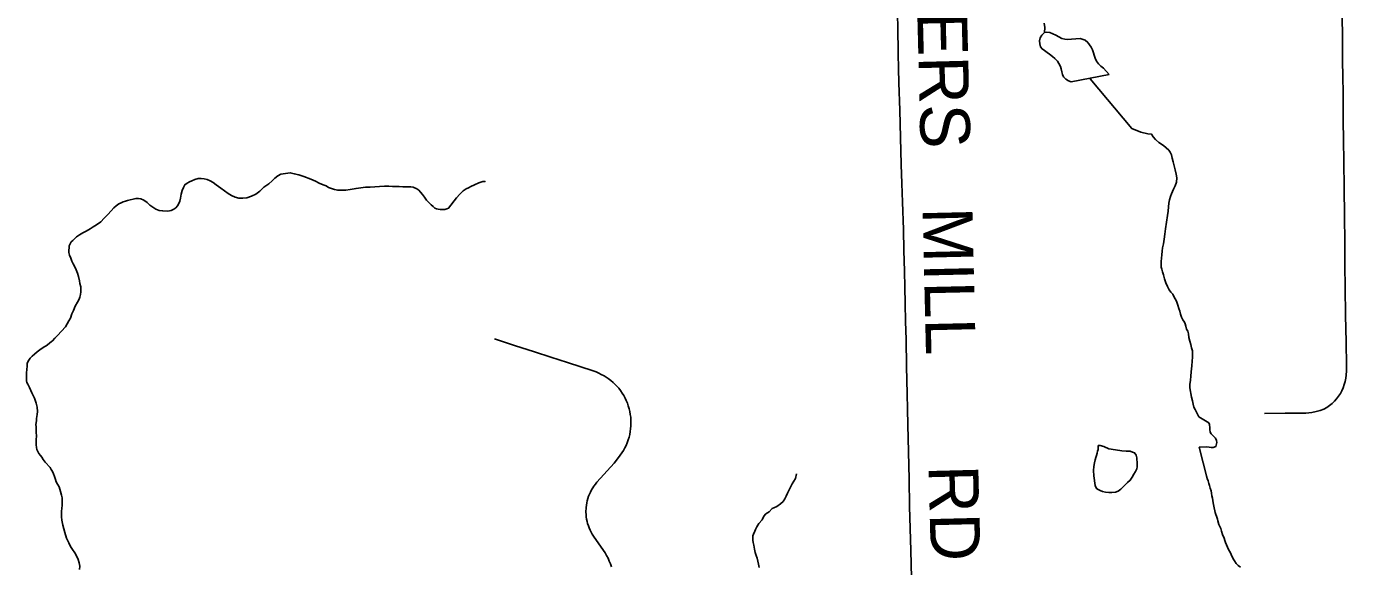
# Model space of a CAD drawing. Extents: x 103424 to 286016, y 38711 to 110967.
# Drawn here: x 125365 to 133370, y 84863 to 88138 of the extents above; entities that cross this region are included whole.
import ezdxf

# ---------------------------------------------------------------- set-up
doc = ezdxf.new("R2010")
doc.units = 0
for name, color, linetype in [('GM_X_Minor_Lake', 7, 'Continuous'), ('GM_X_Minor_River', 7, 'Continuous'), ('GM_X_Township_Road', 7, 'Continuous'), ('GM_X_Township_Road_Text', 7, 'Continuous')]:
    doc.layers.add(name, color=color, linetype=linetype)

msp = doc.modelspace()

# ---------------------------------------------------------------- linework, layer by layer
at = {"layer": 'GM_X_Minor_Lake'}
msp.add_line((131700.9, 87802.5), (131930.2, 87846.7), dxfattribs=at)
for points in [[(131753.7, 88065), (131675.8, 88058.2), (131661.7, 88060.1), (131643.5, 88064), (131607.2, 88083.9), (131570.8, 88099.8), (131552.7, 88101.7), (131538.6, 88099.6), (131522.6, 88085.4), (131512.7, 88069.2), (131508.8, 88051), (131510.9, 88032.9), (131515, 88014.7), (131523.2, 88000.7), (131537.3, 87990.7), (131553.5, 87978.7), (131567.7, 87968.7), (131585.9, 87954.7), (131600.1, 87942.7), (131616.3, 87926.7), (131624.4, 87912.7), (131634.6, 87894.6), (131638.7, 87880.5), (131642.9, 87862.4), (131647, 87846.3), (131653.2, 87832.2), (131667.4, 87818.2), (131683.5, 87808.2), (131700.9, 87802.5)], [(131930.2, 87846.7), (131896.4, 87884.3), (131880.2, 87896.3), (131866, 87910.3), (131853.8, 87926.3), (131845.6, 87944.4), (131839.5, 87962.5), (131835.4, 87976.6), (131829.2, 87994.7), (131821, 88010.8), (131810.9, 88026.8), (131800.7, 88040.9), (131784.5, 88054.9), (131753.7, 88065)], [(131863.7, 85596.2), (131864, 85571.9), (131860, 85561.8), (131858.2, 85549.7), (131854.3, 85535.5), (131850.4, 85523.3), (131844.5, 85509.1), (131840.7, 85490.9), (131836.9, 85468.7), (131835.2, 85444.4), (131837.5, 85412.1), (131846.3, 85353.6), (131852.6, 85335.5), (131862.7, 85329.5), (131874.9, 85323.6), (131889.1, 85317.7), (131907.4, 85313.8), (131927.6, 85312), (131945.7, 85312.2), (131967.9, 85314.4), (131984, 85320.6), (132002.1, 85332.9), (132014.1, 85343.2), (132028, 85357.4), (132042, 85371.7), (132058, 85386), (132069.9, 85404.3), (132079.8, 85422.6), (132089.7, 85438.9), (132097.6, 85455.1), (132099.5, 85467.2), (132099.3, 85481.4), (132099.2, 85495.5), (132099, 85511.7), (132098.8, 85521.8), (132094.6, 85537.9), (132084.4, 85551.9), (132072.2, 85555.8), (132058, 85561.8), (132047.9, 85561.7), (132033.8, 85561.5), (132007.5, 85565.3), (131969.4, 85569.6)], [(131969.4, 85569.6), (131928.5, 85576.6), (131898.1, 85590.5), (131875.8, 85596.3), (131863.7, 85596.2)]]:
    msp.add_lwpolyline(points, dxfattribs=at)
at = {"layer": 'GM_X_Minor_River'}
for points in [[(131537.1, 88156.4), (131539.4, 88130.2), (131538.6, 88099.6)], [(131814.2, 87820.5), (132067.6, 87519.3), (132122.4, 87495.6), (132164.9, 87485.9), (132187.2, 87484.1), (132197.5, 87468.1), (132211.8, 87452.1), (132232.2, 87434.1), (132260.7, 87416.2), (132277, 87402.2), (132291.3, 87388.2), (132299.5, 87374.2), (132307.8, 87358.1), (132312.1, 87337.9), (132318.4, 87315.8), (132324.7, 87291.6), (132331.1, 87267.4), (132337.4, 87241.2), (132339.7, 87219), (132338, 87192.7), (132330.2, 87170.4), (132320.3, 87150.1), (132314.4, 87135.9), (132308.5, 87121.7), (132302.7, 87105.5), (132296.8, 87085.3), (132293, 87065), (132289.2, 87042.8), (132287.5, 87016.5), (132283.8, 86990.2), (132272.6, 86909.3), (132268.9, 86878.9), (132263.2, 86848.6), (132259.5, 86820.2), (132253.7, 86795.9), (132251.9, 86775.7), (132250.2, 86753.5), (132248.4, 86733.3), (132246.6, 86713.1), (132244.8, 86694.9), (132245, 86678.7), (132249.2, 86666.6), (132253.4, 86650.5), (132259.7, 86630.4), (132266, 86606.2), (132274.4, 86582), (132284.7, 86559.9), (132295.1, 86539.8), (132305.3, 86525.8), (132315.6, 86513.7), (132321.8, 86499.7), (132330.1, 86485.6), (132338.3, 86471.6), (132342.5, 86459.5), (132346.6, 86447.4), (132352.9, 86427.3), (132359.2, 86411.2), (132363.4, 86393), (132369.7, 86374.9), (132378, 86358.8), (132386.2, 86344.8), (132390.4, 86334.7), (132394.6, 86320.6), (132398.8, 86302.5), (132407, 86290.4), (132411.3, 86274.3), (132413.6, 86252.1), (132419.9, 86230), (132426.1, 86209.8), (132430.4, 86189.7), (132434.7, 86171.5), (132434.9, 86153.3), (132435.1, 86133.1), (132433.4, 86108.9), (132431.7, 86080.6), (132428.1, 86044.2), (132426.4, 86017.9), (132422.6, 85993.6), (132418.9, 85967.3), (132419.1, 85947.1), (132429.9, 85890.7), (132436.2, 85866.5), (132440.5, 85846.4), (132444.7, 85828.2), (132450.9, 85814.1), (132473.2, 85770.8)], [(125400.3, 86137.9), (125414.3, 86150.2), (125430.2, 86164.5), (125446.3, 86176.7), (125466.3, 86191.1), (125490.4, 86205.5), (125506.4, 86219.8), (125522.4, 86232.1), (125538.3, 86248.4), (125554.3, 86262.7), (125602.2, 86315.7), (125612.1, 86333.9), (125622, 86352.2), (125631.9, 86368.5), (125639.6, 86394.8), (125651.5, 86415.1), (125661.3, 86441.5), (125675.2, 86465.9), (125685.1, 86484.2), (125689, 86496.3), (125692.8, 86512.5), (125694.7, 86528.7), (125694.5, 86542.8), (125694.3, 86559), (125690, 86579.2), (125687.8, 86595.3), (125681.5, 86621.5), (125675.2, 86641.6), (125666.9, 86661.7), (125658.6, 86679.8), (125648.3, 86697.9), (125640, 86714), (125633.7, 86732.1), (125627.4, 86750.2), (125623.2, 86766.4), (125623.1, 86780.5), (125624.9, 86794.7), (125624.8, 86806.8), (125630.7, 86819), (125636.6, 86831.1), (125646.6, 86839.3), (125656.6, 86849.5), (125668.6, 86861.8), (125686.6, 86874.1), (125706.7, 86886.4), (125726.7, 86896.7), (125750.8, 86911.1), (125770.9, 86921.4), (125790.9, 86933.7), (125817, 86952.1), (125836.9, 86974.5), (125858.9, 86997), (125878.8, 87019.4), (125894.8, 87037.7), (125908.8, 87050), (125924.8, 87062.3), (125938.8, 87068.5), (125950.9, 87074.7), (125965, 87078.8), (125977.1, 87083), (126029.4, 87093.6), (126045.6, 87093.8), (126059.8, 87091.9), (126078, 87084), (126096.4, 87070), (126112.7, 87054), (126131, 87042.1), (126149.3, 87030.2), (126169.6, 87022.3), (126191.9, 87018.5), (126222.2, 87016.8), (126242.3, 87021), (126258.4, 87029.2), (126270.4, 87037.4), (126280.4, 87049.7), (126290.3, 87063.9), (126296.2, 87078.1), (126300.1, 87096.3), (126303.8, 87120.6), (126309.6, 87142.9), (126317.5, 87161.1), (126325.4, 87177.4), (126339.4, 87187.6), (126353.4, 87195.8), (126367.5, 87202), (126385.6, 87210.3), (126405.7, 87214.5), (126423.9, 87214.7), (126442.1, 87212.9), (126460.3, 87209), (126478.6, 87201.1), (126496.9, 87191.2), (126515.2, 87177.2), (126543.7, 87157.3), (126566.1, 87141.4), (126588.5, 87125.4), (126608.9, 87111.5), (126631.2, 87101.6), (126653.5, 87095.8), (126677.7, 87096), (126702, 87098.3)], [(126702, 87098.3), (126730.1, 87108.7), (126756.2, 87121.1), (126780.3, 87139.5), (126804.2, 87163.9), (126834.3, 87182.4), (126854.3, 87200.8), (126872.3, 87217.1), (126890.3, 87231.5), (126908.3, 87241.7), (126964.8, 87250.4), (126989.1, 87244.6), (127017.5, 87236.8), (127047.9, 87227), (127090.5, 87211.2), (127118.9, 87199.4), (127141.2, 87187.5), (127163.6, 87177.6), (127181.8, 87171.7), (127196.1, 87161.8), (127214.3, 87153.9), (127232.6, 87148), (127252.8, 87144.2), (127277.1, 87144.4), (127301.3, 87144.6), (127327.5, 87148.9), (127363.8, 87155.4), (127392, 87159.7), (127420.3, 87162), (127448.5, 87162.3), (127476.8, 87164.6), (127507, 87166.9), (127537.3, 87169.2), (127563.6, 87169.5), (127585.8, 87167.7), (127606, 87167.9), (127626.2, 87166.1), (127648.5, 87164.3), (127664.6, 87164.4), (127682.8, 87164.6), (127696.9, 87164.7), (127711.1, 87162.9), (127733.4, 87153), (127743.6, 87145), (127753.8, 87133), (127766.1, 87119), (127778.4, 87102.9), (127790.8, 87084.9), (127807.1, 87068.9), (127819.4, 87054.9), (127831.6, 87044.9), (127841.8, 87034.9), (127852, 87030.9), (127862.1, 87029), (127874.2, 87027.1), (127888.4, 87027.3), (127902.5, 87027.4), (127914.6, 87031.6), (127924.6, 87035.7), (127972.4, 87098.8), (127992.3, 87121.2), (128014.3, 87141.6), (128032.4, 87151.9), (128046.4, 87158.1), (128060.5, 87166.3), (128082.6, 87176.7), (128108.7, 87189), (128132.8, 87197.4), (128146.9, 87197.5), (128146.9, 87197.5)], [(125687.9, 84843.9), (125689.7, 84866.1), (125685.4, 84886.3), (125679.1, 84906.4), (125668.8, 84928.5), (125658.5, 84946.6), (125644.1, 84966.7), (125631.8, 84984.7), (125621.4, 85006.8), (125609, 85035), (125598.5, 85069.2), (125585.8, 85113.6), (125579.4, 85143.8), (125577.2, 85164), (125577, 85182.2), (125578.8, 85198.3), (125580.6, 85214.5), (125582.4, 85234.7), (125582.1, 85259), (125581.9, 85279.2), (125577.7, 85295.3), (125571.3, 85317.4), (125562.9, 85345.6), (125552.7, 85361.7), (125546.4, 85375.8), (125542.2, 85389.9), (125536, 85408), (125529.7, 85424.1), (125523.5, 85438.2), (125515.3, 85450.2), (125509.1, 85462.3), (125478.4, 85496.3), (125466.1, 85512.3), (125457.8, 85526.4), (125449.6, 85536.4), (125441.4, 85548.5), (125435.2, 85560.5), (125429, 85572.6), (125426.9, 85584.7), (125424.7, 85600.8), (125424.3, 85631.1), (125426.1, 85655.4), (125423.8, 85675.5), (125423.6, 85693.7), (125423.4, 85709.9), (125423.2, 85724), (125425.1, 85734.1), (125427, 85748.3), (125426.9, 85760.4), (125428.7, 85772.6), (125430.6, 85784.7), (125432.4, 85802.9), (125430.1, 85829.1), (125423.8, 85853.3), (125413.3, 85883.5), (125398.8, 85915.7), (125384.3, 85947.9), (125374, 85968), (125367.8, 85978), (125365.6, 85988.1), (125365.4, 86008.3), (125365.1, 86036.6), (125366.9, 86056.8), (125368.7, 86077), (125370.5, 86093.2), (125374.4, 86103.3), (125380.3, 86113.5), (125388.3, 86125.7), (125400.3, 86137.9)], [(132473.2, 85770.8), (132534.4, 85734.1), (132538.6, 85724.1), (132541, 85703.9), (132541.2, 85693.8), (132543.5, 85677.7), (132549.7, 85667.7), (132562.1, 85653.8), (132574.4, 85641.9), (132580.7, 85627.9), (132583, 85615.8), (132577.3, 85591.4), (132561.3, 85585.1), (132549.2, 85584.9), (132537.1, 85586.7), (132522.9, 85588.5), (132477.1, 85586.3)], [(132477.1, 85586.3), (132524.3, 85396.6), (132520, 85414.7), (132524.3, 85396.6), (132530.7, 85382.5), (132535, 85366.5), (132539.2, 85354.4), (132543.5, 85338.3), (132547.9, 85322.2), (132550.1, 85308.1), (132552.5, 85292), (132556.7, 85278), (132559, 85263.8), (132561.3, 85249.8), (132563.5, 85239.7), (132565.7, 85229.6), (132572.4, 85191.4), (132576.7, 85179.3), (132580.9, 85167.3), (132587.3, 85149.2), (132589.5, 85139.1), (132596, 85117), (132602.2, 85105), (132606.5, 85093), (132610.8, 85076.9), (132617.2, 85056.8), (132627.7, 85034.8), (132632, 85020.7), (132636.2, 85008.7), (132642.5, 84994.6), (132648.8, 84980.6), (132653.1, 84966.6), (132659.4, 84956.6), (132667.7, 84942.6), (132671.9, 84930.5), (132678.2, 84920.5), (132682.4, 84910.5), (132690.7, 84896.5), (132701.1, 84880.6), (132713.4, 84868.7), (132727.7, 84858.8)], [(130033.8, 85424.5), (130028, 85396.1), (130018.1, 85379.9), (130008.2, 85363.6), (129980.6, 85306.8), (129972.7, 85288.5), (129964.8, 85274.3), (129952.9, 85258), (129936.9, 85243.7), (129914.9, 85227.3), (129896.8, 85219.1), (129886.7, 85214.9), (129868.8, 85194.5), (129848.7, 85182.2), (129836.8, 85168), (129826.9, 85145.7), (129807, 85123.2), (129793.1, 85102.9), (129785.2, 85086.7), (129781.3, 85076.5), (129773.4, 85058.3), (129769.5, 85048.1), (129769.7, 85034), (129769.8, 85021.9), (129772, 85007.7), (129776.2, 84991.6), (129780.5, 84967.4), (129784.8, 84947.3), (129789, 84929.1), (129795.3, 84913), (129799.5, 84894.9), (129803.8, 84876.7), (129808.1, 84856.6)]]:
    msp.add_lwpolyline(points, dxfattribs=at)
at = {"layer": 'GM_X_Township_Road'}
for points in [[(130732.3, 84795.1), (130727.7, 84960.1), (130723.9, 85093.9), (130720.2, 85227.7), (130716.8, 85392.8), (130713.3, 85557.8), (130709.9, 85722.8), (130707.9, 85816.2), (130706, 85909.7), (130702.3, 86074.7), (130698.6, 86239.8), (130696.1, 86349), (130693.6, 86458.3), (130691.1, 86555.7), (130688.6, 86653.2), (130685.7, 86779.8), (130682.8, 86906.5), (130677, 87071.5), (130673.1, 87185.5), (130669.1, 87299.6), (130664.6, 87464.6), (130660.1, 87629.6), (130655.6, 87794.6), (130653.2, 87882.7), (130650.8, 87970.9), (130648, 88135.9), (130645.8, 88271.4)], [(132871.4, 85790.5), (132997.5, 85791.8), (133123.6, 85793), (133158.4, 85796.8), (133185, 85802.5), (133209.7, 85809), (133231.4, 85817.6), (133249.8, 85827.4), (133266.2, 85838.6), (133281.6, 85851), (133295.9, 85864.6), (133309, 85879.3), (133321.1, 85895), (133332.5, 85912.4), (133341.3, 85929), (133349.3, 85947), (133355.9, 85965.6), (133360.9, 85984.7), (133364.7, 86004.2), (133366.7, 86023.8), (133369.2, 86049.2), (133370, 86082.2), (133366.7, 86222.4), (133364.4, 86387.5), (133362.2, 86552.5), (133360.3, 86689), (133358.5, 86825.6), (133356.6, 86990.7), (133354.8, 87155.7), (133352.9, 87320.8), (133351.5, 87444.9), (133350.1, 87569), (133348.3, 87734.1), (133347.2, 87832.8), (133346.1, 87931.4), (133344.6, 88067.4), (133343, 88203.5)], [(128912.1, 84861.8), (128906.3, 84879.3), (128899.5, 84896.4), (128892, 84913.1), (128883.4, 84929.5), (128874.1, 84945.4), (128864.1, 84960.7), (128803.7, 85047.1), (128796.1, 85058.9), (128789.4, 85071.1), (128783.1, 85083.7), (128777.5, 85096.6), (128772.5, 85109.8), (128768.2, 85123.1), (128764.7, 85136.7), (128762, 85150.5), (128759.9, 85164.4), (128758.7, 85178.4), (128757.9, 85192.4), (128759, 85220.4), (128760.5, 85234.4), (128763, 85248.2), (128766, 85262), (128769.8, 85275.4), (128774.1, 85288.8), (128779.4, 85301.8), (128785.2, 85314.6), (128791.7, 85327), (128798.8, 85339.2), (128806.6, 85350.9), (128814.9, 85362.1), (128824.2, 85373.5), (128928.3, 85489.2), (128955.4, 85523.5), (128966, 85537.3), (128976.1, 85551.7), (128985.2, 85566.5), (128993.7, 85581.8), (129001.3, 85597.5), (129007.9, 85613.6), (129013.9, 85630.1), (129019, 85646.8), (129023, 85663.7), (129026.3, 85680.9), (129028.5, 85698.2), (129030.1, 85715.6), (129030.6, 85733), (129029.1, 85767.9), (129026.8, 85785.2), (129023.6, 85802.4), (129019.8, 85819.4), (129014.8, 85836.2), (129009, 85852.7), (129002.5, 85868.8), (128994.9, 85884.6), (128986.6, 85900), (128977.5, 85914.9), (128967.7, 85929.3), (128957.2, 85943.3), (128946.1, 85956.5), (128934.3, 85967.4), (128922.6, 85978.5), (128908.5, 85991.2), (128892.8, 86002), (128868.2, 86018.2), (128851, 86026.6), (128836, 86035.1), (128819.1, 86042.6), (128802, 86048.6), (128645, 86099.5), (128545.3, 86131.8), (128445.6, 86164.1), (128324.1, 86203.8), (128202.6, 86243.5)]]:
    msp.add_lwpolyline(points, dxfattribs=at)

# ---------------------------------------------------------------- texts
at = {"layer": 'GM_X_Township_Road_Text'}
for s, rotation, p in [('FOWLERS', 271.4542, (130737.1, 89390)), ('MILL', 271.33903, (130799, 87038.3)), ('RD', 271.47632, (130834.5, 85474.9))]:
    msp.add_text(s, height=301.87, rotation=rotation, dxfattribs=at).set_placement(p)

doc.saveas('drawing.dxf')
